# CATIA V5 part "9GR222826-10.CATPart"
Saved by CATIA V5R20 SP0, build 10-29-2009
Part number: 9GR222826-10
Revision: ANY
Definition: UNKNOWN
Nomenclature: 9GR222826-10
Source: Unknown
Bounding box of the stored display mesh (mm): x -12.979 to 12.803, y -23 to 5, z -13 to 13
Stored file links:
  C:\Users\Utente\Desktop\IO LAVORO\3D X SITO CF\CUMSA\3D files GR\GR 222826-10\9GR222826-10.CATPart
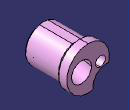
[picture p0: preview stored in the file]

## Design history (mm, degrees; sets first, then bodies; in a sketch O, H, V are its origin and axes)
Body1 "Cortar-Extruir7" (main body)
  Solid1: solid without history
